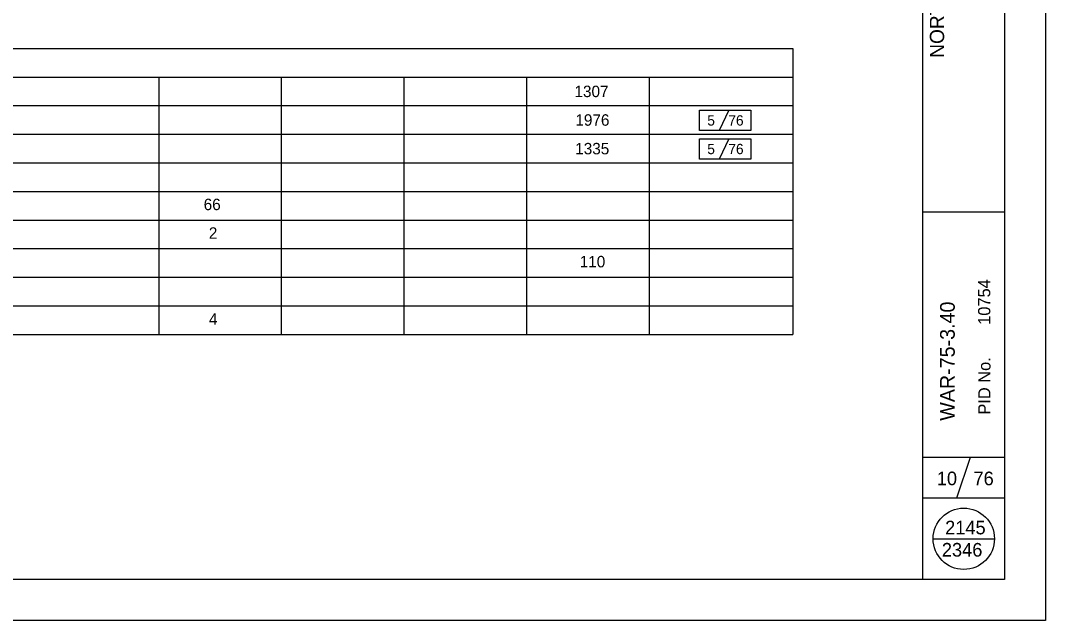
# Model space of a CAD drawing. Extents: x 0 to 34, y 0 to 22.
# Drawn here: x 21.46 to 34, y 0 to 7.34 of the extents above; entities that cross this region are included whole.
import ezdxf

# ---------------------------------------------------------------- set-up
doc = ezdxf.new("R2010")
doc.units = 0
for name, color, linetype in [('BR_P_Gen_Text', 7, 'Continuous'), ('BR_P_Sub_Text', 7, 'Continuous'), ('SH_Border', 7, 'Continuous'), ('SH_Cut_Line', 7, 'Continuous'), ('SH_Data', 7, 'Continuous'), ('SH_Text', 7, 'Continuous')]:
    doc.layers.add(name, color=color, linetype=linetype)

msp = doc.modelspace()

# ---------------------------------------------------------------- linework, layer by layer
at = {"layer": 'BR_P_Gen_Text'}
for p, q in [((30.125, 6.244), (30.009, 5.994)), ((30.125, 5.894), (30.009, 5.644))]:
    msp.add_line(p, q, dxfattribs=at)
for points in [[(29.768, 6.244), (30.394, 6.244), (30.394, 5.994), (29.768, 5.994)], [(29.768, 6.244), (30.394, 6.244), (30.394, 5.994), (29.768, 5.994)], [(29.768, 5.894), (30.394, 5.894), (30.394, 5.644), (29.768, 5.644)], [(29.768, 5.894), (30.394, 5.894), (30.394, 5.644), (29.768, 5.644)]]:
    msp.add_lwpolyline(points, close=True, dxfattribs=at)
at = {"layer": 'SH_Border'}
for p, q in [((32.5, 0.5), (32.5, 21.5)), ((32.5, 0.5), (32.5, 21.5)), ((32.5, 0.5), (32.5, 21.5)), ((32.5, 5), (33.5, 5)), ((32.5, 5), (33.5, 5)), ((32.5, 5), (33.5, 5)), ((32.5, 2), (33.5, 2)), ((32.917, 1.5), (33.083, 2)), ((32.5, 1.5), (33.5, 1.5))]:
    msp.add_line(p, q, dxfattribs=at)
msp.add_lwpolyline([(2, 21.5), (33.5, 21.5), (33.5, 0.5), (2, 0.5)], close=True, dxfattribs=at)
at = {"layer": 'SH_Cut_Line'}
msp.add_lwpolyline([(0, 22), (34, 22), (34, 0), (0, 0)], close=True, dxfattribs=at)
at = {"layer": 'SH_Data'}
msp.add_line((32.625, 1), (33.375, 1), dxfattribs=at)
msp.add_line((32.625, 1), (33.375, 1), dxfattribs=at)
msp.add_line((32.625, 1), (33.375, 1), dxfattribs=at)
msp.add_circle((33, 1), 0.375, dxfattribs=at)
at = {"layer": 'SH_Text'}
for p, q in [((3.59, 7), (30.91, 7)), ((3.59, 7), (30.91, 7)), ((30.91, 7), (30.91, 3.5)), ((3.59, 6.65), (30.91, 6.65)), ((23.15, 6.65), (23.15, 3.5)), ((24.65, 6.65), (24.65, 3.5)), ((26.15, 6.65), (26.15, 3.5)), ((27.65, 6.65), (27.65, 3.5)), ((29.15, 6.65), (29.15, 3.5)), ((3.59, 6.3), (30.91, 6.3)), ((3.59, 5.95), (30.91, 5.95)), ((3.59, 5.6), (30.91, 5.6)), ((3.59, 5.25), (30.91, 5.25)), ((3.59, 4.9), (30.91, 4.9)), ((3.59, 4.55), (30.91, 4.55)), ((3.59, 4.2), (30.91, 4.2)), ((3.59, 3.85), (30.91, 3.85)), ((3.59, 3.5), (30.91, 3.5))]:
    msp.add_line(p, q, dxfattribs=at)

# ---------------------------------------------------------------- texts
at = {"layer": 'BR_P_Gen_Text'}
for s, p in [(' 5', (29.815, 6.056)), ('76', (30.119, 6.056)), (' 5', (29.815, 5.706)), ('76', (30.119, 5.706))]:
    msp.add_text(s, height=0.1259, dxfattribs=at).set_placement(p)
at = {"layer": 'BR_P_Sub_Text'}
msp.add_text('WAR-75-3.40', height=0.18, rotation=90, dxfattribs=at).set_placement((32.89, 2.444))
at = {"layer": 'SH_Data'}
for s, height, p in [('     NORTHBOUND ESTIMATED QUANTITIES    ', 0.175, (32.76, 6.56)), ('10754', 0.15, (33.325, 3.618)), ('PID No.', 0.15, (33.327, 2.519))]:
    msp.add_text(s, height=height, rotation=90, dxfattribs=at).set_placement(p)
for s, p in [('10', (32.67, 1.655)), ('76', (33.119, 1.655)), ('2145', (32.772, 1.054)), ('2346', (32.732, 0.782))]:
    msp.add_text(s, height=0.1666, dxfattribs=at).set_placement(p)
at = {"layer": 'SH_Text'}
for s, p in [('1307', (28.237, 6.404)), ('1976', (28.248, 6.054)), ('1335', (28.246, 5.704)), ('66', (23.7, 5.021)), ('2', (23.763, 4.671)), ('110', (28.301, 4.321)), ('4', (23.764, 3.618))]:
    msp.add_text(s, height=0.14, dxfattribs=at).set_placement(p)

doc.saveas('drawing.dxf')
